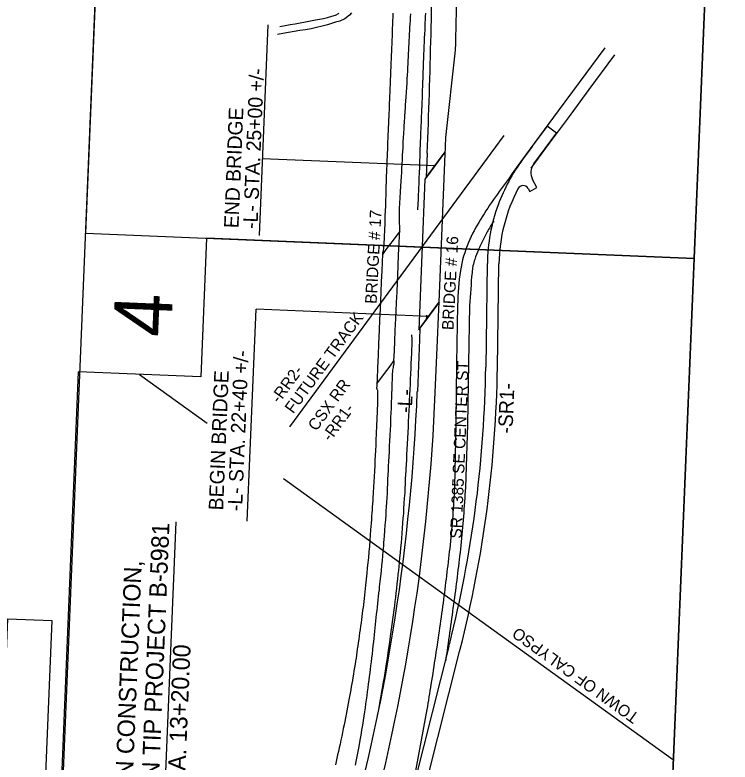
# Model space of a CAD drawing. Extents: x 2264506 to 2267635, y 507918 to 512596.
# Drawn here: x 2265629 to 2266862, y 509740 to 511027 of the extents above; entities that cross this region are included whole.
import ezdxf

# ---------------------------------------------------------------- set-up
doc = ezdxf.new("R2010")
doc.units = 0
for name, color, linetype in [('COGO Default Parcel', 7, 'Continuous'), ('Default', 7, 'Continuous'), ('Exist Structure Minor Drop Inlet Cogo Number', 7, 'Continuous'), ('Pattern 10', 7, 'Continuous'), ('Prop EOT Dash', 7, 'Continuous'), ('Prop Guardrail', 7, 'Continuous'), ('Prop Lane Arrow CELL', 7, 'Continuous'), ('Prop Structure Anchor Unit CELL', 7, 'Continuous'), ('Prop Superelevation Label', 7, 'Continuous')]:
    doc.layers.add(name, color=color, linetype=linetype)

msp = doc.modelspace()

# ---------------------------------------------------------------- linework, layer by layer
at = {"layer": 'COGO Default Parcel'}
for points in [[(2266800.3, 510607.5), (2266862.2, 512106.3), (2266024.4, 512140.9), (2266014.5, 511901.8), (2265803.2, 511910.6), (2265751.2, 510650.9)], [(2266744.1, 509248.2), (2266800.3, 510607.5), (2265959.7, 510642.3), (2265949.8, 510403.2), (2265738.5, 510412), (2265692.2, 509291.7)]]:
    msp.add_lwpolyline(points, close=True, dxfattribs=at)
at = {"layer": 'Default'}
for points in [[(2265844.2, 510407.6), (2265960.8, 510323.5)], [(2266092.5, 510228.4), (2266763.1, 509744.3)]]:
    msp.add_lwpolyline(points, dxfattribs=at)
msp.add_lwpolyline([(2265575.7, 508983.7), (2265617.1, 509986.5), (2265692.9, 509983.3), (2265651.5, 508980.6)], close=True, dxfattribs=at)
at = {"layer": 'Exist Structure Minor Drop Inlet Cogo Number'}
for p, q in [((2266065.3, 511009.8), (2266050.3, 510646.7)), ((2266353.1, 510766.8), (2266055.8, 510779.1)), ((2266029.9, 510154.4), (2266045, 510519.7)), ((2266342.4, 510507.4), (2266045, 510519.7)), ((2265884.5, 509605.1), (2265907.1, 510153.7))]:
    msp.add_line(p, q, dxfattribs=at)
at = {"layer": 'Pattern 10'}
msp.add_line((2266103.3, 510317.2), (2266472.5, 510819.4), dxfattribs=at)
at = {"layer": 'Prop EOT Dash'}
msp.add_lwpolyline([(2265695, 509291.6), (2265813.1, 512149.6), (2266862.2, 512106.3), (2266744.1, 509248.2)], close=True, dxfattribs=at)
at = {"layer": 'Prop Guardrail'}
for p, q in [((2266372.1, 510815.9), (2266389, 510966.1)), ((2266547, 510835.3), (2266521.2, 510800.8)), ((2266563.1, 510823.4), (2266547, 510835.3)), ((2266520.9, 510800), (2266504.6, 510778)), ((2266521.2, 510800.8), (2266520.7, 510800)), ((2266520.7, 510800), (2266520.9, 510800)), ((2266338.3, 510746.6), (2266371.2, 510791.3)), ((2266340, 510788.8), (2266338.3, 510746.6)), ((2266528.9, 510729.8), (2266521.7, 510743.6)), ((2266513.9, 510728.1), (2266517.2, 510722.9)), ((2266517.2, 510722.9), (2266528.9, 510729.8)), ((2266462.4, 510699.4), (2266462.2, 510699.5)), ((2266443.7, 510598.5), (2266441.7, 510463)), ((2266461.7, 510462.2), (2266463.7, 510598.2)), ((2266463.7, 510598.2), (2266463.7, 510598.2)), ((2266360.4, 510531.9), (2266327.6, 510487.2)), ((2266359.4, 510507), (2266360.4, 510531.9)), ((2266357.7, 510466.5), (2266359.4, 510507)), ((2266327.6, 510487.2), (2266326.8, 510467.8)), ((2266326.8, 510467.8), (2266323.1, 510377.9)), ((2266354, 510376.6), (2266357.7, 510466.5)), ((2266357.7, 510466.5), (2266357.7, 510466.5)), ((2266441.7, 510463), (2266441.1, 510420.2)), ((2266461.1, 510419.9), (2266461.7, 510462.2)), ((2266377.5, 509938.8), (2266309.8, 509670.6)), ((2266329.1, 509665.7), (2266396, 509930.1)), ((2266396, 509930.1), (2266396.9, 509933.9))]:
    msp.add_line(p, q, dxfattribs=at)
msp.add_lwpolyline([(2266523.7, 510770.2), (2266523.7, 510770.2), (2266563.1, 510823.4)], dxfattribs=at)
for centre, radius, start, end in [((2255163.6, 511250.5), 11186, 357.63416, 359.73109), ((2255163.6, 511250.5), 11229, 358.54854, 359.57091), ((2255163.6, 511250.5), 11217, 357.65367, 357.77953), ((2266753.7, 510593.4), 310, 143.4649, 160), ((2266543.8, 510755.3), 25, 143.465, 207.8122), ((2266753.7, 510593.4), 290, 152.4536, 179.0609), ((2266505.4, 510722.9), 10, 31.5739, 152.4536), ((2266753.7, 510593.9), 310, 160.0914, 179.154), ((2264351.3, 510451.1), 2090, 346.3966, 359.154), ((2264351.3, 510451.1), 2110, 345.8113, 359.154), ((2262840, 510521.8), 3486, 344.7422, 357.6342), ((2262840, 510521.8), 3517, 344.7004, 357.6342), ((2264351.3, 510451.1), 2090, 345.8113, 346.3966)]:
    msp.add_arc(centre, radius, start, end, dxfattribs=at)
at = {"layer": 'Prop Lane Arrow CELL'}
for p, q in [((2266485.2, 510751.2), (2266502, 510774.5)), ((2266485.2, 510751.2), (2266484.5, 510750.3)), ((2266339.5, 509830.1), (2266317, 509707.7))]:
    msp.add_line(p, q, dxfattribs=at)
for points in [[(2266209.8, 511030.6), (2266206.2, 511026.7), (2266198, 511020.4), (2266189.2, 511016.5), (2266182.2, 511014.3), (2266175.3, 511012.2), (2266168.4, 511010), (2266158.9, 511007.7), (2266149.5, 511005.4), (2266140, 511003.1), (2266130.3, 511001.5), (2266120.6, 510999.9), (2266110.8, 510998.3), (2266101.1, 510996.7), (2266091.4, 510995.1), (2266081.7, 510993.5)], [(2266086.2, 511007.1), (2266095, 511008.7), (2266103.7, 511010.3), (2266112.5, 511011.9), (2266121.2, 511013.5), (2266130, 511015.1), (2266138.7, 511016.7), (2266147.4, 511018.4), (2266154.3, 511019.7), (2266161.2, 511021.1), (2266168.1, 511022.4), (2266175.9, 511024.6), (2266181.9, 511026.3), (2266188.1, 511030.2)], [(2266280.9, 511029.9), (2266280.7, 511023.5), (2266280.4, 511017), (2266280.2, 511010.3), (2266279.9, 511003.5), (2266279.6, 510996.8), (2266279.4, 510990.1), (2266279.1, 510983.5), (2266278.8, 510976.9), (2266278.5, 510970.4), (2266278.3, 510964), (2266278, 510957.7), (2266277.8, 510951.3), (2266277.6, 510944.6), (2266277.3, 510937.5), (2266277, 510930), (2266276.7, 510922.5), (2266276.4, 510915), (2266276.1, 510907.7), (2266275.7, 510900.6), (2266275.4, 510893.7), (2266275.2, 510887.1), (2266274.9, 510881), (2266274.7, 510875.2), (2266274.4, 510869.5), (2266274.2, 510863.7), (2266274, 510857.8), (2266273.8, 510851.7), (2266273.5, 510845.6), (2266273.3, 510839.4), (2266273, 510833.2), (2266272.7, 510827), (2266272.4, 510820.8), (2266272.2, 510814.4), (2266271.9, 510807.9), (2266271.6, 510801.4), (2266271.4, 510795), (2266271.1, 510788.9), (2266270.9, 510783.3), (2266270.7, 510778.1), (2266270.5, 510772.9), (2266270.3, 510767.5), (2266270.1, 510761.8), (2266269.8, 510755.9), (2266269.6, 510749.9), (2266269.4, 510743.9), (2266269.2, 510738), (2266269, 510732.1), (2266268.8, 510726.3), (2266268.7, 510720.6), (2266268.5, 510715), (2266268.3, 510709.5), (2266268.1, 510704), (2266267.9, 510698.4), (2266267.6, 510688.9), (2266267.3, 510681.2), (2266267.1, 510675.6), (2266266.9, 510670.1), (2266266.8, 510664.7), (2266266.6, 510659.3), (2266266.3, 510653.8), (2266266.1, 510648.3), (2266265.8, 510642.6), (2266265.3, 510633.2), (2266265, 510628), (2266264.6, 510624.7), (2266264, 510621.1), (2266263.4, 510618.1), (2266263.1, 510616.3), (2266263, 510615.3), (2266263, 510614.8)], [(2266292.6, 510654.5), (2266292.6, 510656), (2266292.6, 510658.8), (2266292.6, 510662.7), (2266292.4, 510667.6), (2266292.2, 510673), (2266292.1, 510678.9), (2266292.2, 510685.6), (2266292.5, 510693.6), (2266292.9, 510702.5), (2266293.4, 510712), (2266294, 510721.9), (2266294.5, 510731.8), (2266295.1, 510740.8), (2266295.6, 510747.7), (2266296.1, 510756.2), (2266296.5, 510762.4), (2266296.9, 510769.9), (2266297.3, 510777.8), (2266297.7, 510785.1), (2266298.1, 510791.9), (2266298.4, 510798), (2266298.6, 510803.8), (2266298.9, 510809.2), (2266299.2, 510814.4), (2266299.8, 510823.7), (2266300.2, 510830.7), (2266300.6, 510835.7), (2266301, 510842.4), (2266301.5, 510851.1), (2266302.2, 510860.9), (2266302.5, 510866.1), (2266302.9, 510871.9), (2266303.3, 510878.3), (2266303.7, 510885.6), (2266304.3, 510893.6), (2266304.8, 510901.8), (2266305.3, 510909.5), (2266305.7, 510916.7), (2266306.1, 510923.4), (2266306.4, 510929.9), (2266306.7, 510936.3), (2266307.1, 510942.5), (2266307.4, 510948.6), (2266307.7, 510954.6), (2266307.9, 510960.5), (2266308.2, 510966.2), (2266308.4, 510971.8), (2266308.7, 510977.3), (2266309, 510982.9), (2266309.3, 510988.5), (2266309.7, 510994.1), (2266310, 510999.9), (2266310.4, 511005.6), (2266310.8, 511011.5), (2266311.1, 511017.5), (2266311.5, 511023.4), (2266311.9, 511029.1)], [(2266337, 511030.2), (2266336.7, 511024.5), (2266336.5, 511019), (2266336.2, 511013.5), (2266335.9, 511007.6), (2266335.7, 511001.1), (2266335.4, 510994.3), (2266335.1, 510987.2), (2266334.8, 510980.1), (2266334.5, 510973.1), (2266334.2, 510966.1), (2266333.9, 510959.5), (2266333.7, 510953.6), (2266333.3, 510943.8), (2266332.9, 510934.6), (2266332.7, 510929.3), (2266332.5, 510923.6), (2266332.3, 510917.5), (2266332, 510911.1), (2266331.8, 510904.4), (2266331.6, 510897.4), (2266331.3, 510890.4), (2266331.1, 510883.5), (2266330.8, 510876.9), (2266330.6, 510870.4), (2266330.3, 510864.1), (2266330.1, 510858.1), (2266329.8, 510852.4), (2266329.6, 510846.9), (2266329.4, 510841.5), (2266329.1, 510836.1), (2266328.9, 510830.7), (2266328.7, 510825.2), (2266328.5, 510819.8), (2266328.3, 510814.5), (2266328.1, 510809.3), (2266327.9, 510804.3), (2266327.5, 510794.3), (2266327.1, 510784.3), (2266326.8, 510774.4), (2266326.5, 510764.6), (2266326.2, 510755), (2266325.8, 510745.5), (2266325.6, 510740.6), (2266325.4, 510735.4), (2266325.2, 510729.7), (2266325, 510723.7), (2266324.7, 510717), (2266324.3, 510709.4), (2266323.8, 510700.8), (2266323.2, 510691.4)], [(2266502, 510774.5), (2266534, 510817.8), (2266566.6, 510861.8), (2266602.5, 510910.4), (2266646.8, 510970.2)], [(2266662.9, 510958), (2266618.8, 510898.4), (2266582.8, 510849.5), (2266550.1, 510805.8), (2266518.6, 510762.7)], [(2266392.5, 510526.9), (2266390.6, 510427), (2266389.2, 510321.4), (2266387, 510213.8)], [(2266413, 510525.8), (2266411.1, 510426.9), (2266409.6, 510321.1), (2266405.9, 510212.7)], [(2266339, 510509.6), (2266338.8, 510506.6), (2266338.5, 510502.1)], [(2266253.2, 509812.9), (2266254.5, 509819.5), (2266256, 509827.5), (2266257.6, 509836.2), (2266259.2, 509844.7), (2266260.6, 509853), (2266262.1, 509861.3), (2266263.6, 509869.5), (2266264.9, 509877.5), (2266266.3, 509885.3), (2266267.5, 509892.9), (2266268.7, 509900.6), (2266270, 509908.9), (2266271.4, 509918), (2266272.8, 509927.6), (2266273.6, 509932.5), (2266275, 509942.2), (2266276.2, 509951.1), (2266277.4, 509959.7), (2266278.6, 509968.3), (2266279.8, 509976.8), (2266281, 509985.2), (2266282.1, 509993.5), (2266283.1, 510001.6), (2266284.1, 510009.3), (2266284.9, 510016.3), (2266285.8, 510023.1), (2266286.7, 510030.6), (2266287.6, 510038.6), (2266288.5, 510046.7), (2266289.4, 510054.8), (2266290.2, 510062.6), (2266290.9, 510069.9), (2266291.6, 510076.6), (2266292.3, 510083.6), (2266293.1, 510091.7), (2266294, 510100.3), (2266294.8, 510108.8), (2266295.5, 510117.1), (2266296.2, 510125.3), (2266296.9, 510133.6), (2266297.6, 510142.4), (2266298.3, 510151.3), (2266298.9, 510159.8), (2266299.5, 510168.1), (2266300, 510176.3), (2266300.6, 510184.8), (2266301.2, 510194.1), (2266301.8, 510203.2), (2266302.2, 510211.3), (2266302.6, 510219), (2266302.9, 510227.1), (2266303.3, 510235.9), (2266303.6, 510240.8), (2266303.9, 510246), (2266304.1, 510251.2), (2266304.7, 510260.8), (2266305.2, 510269.4), (2266305.7, 510278.4), (2266306.2, 510288), (2266306.7, 510297.8), (2266307.2, 510307.6), (2266307.7, 510317.1), (2266308.1, 510326.2), (2266308.5, 510335.5), (2266308.9, 510344.9), (2266309.3, 510354), (2266309.7, 510362.8), (2266310.1, 510371.9), (2266310.5, 510381.3), (2266311, 510390.5), (2266311.4, 510399.5), (2266311.8, 510408.7), (2266312.3, 510418), (2266312.7, 510426.6), (2266313.1, 510434.8), (2266313.6, 510444.2), (2266313.8, 510449.4), (2266314.2, 510458.3), (2266314.4, 510463.8), (2266314.4, 510467.3), (2266314.1, 510470.6), (2266313.8, 510473.5), (2266313.7, 510476)], [(2266282.8, 510430.7), (2266282.8, 510428.2), (2266282.8, 510426.9), (2266282.8, 510426.6), (2266282.7, 510426.1), (2266282.5, 510425), (2266282.1, 510423.5), (2266281.6, 510421.5), (2266281.1, 510419.2), (2266280.7, 510417), (2266280.4, 510414.8), (2266280.1, 510412.8), (2266279.9, 510408.6), (2266279.6, 510400.2), (2266279.2, 510390.3), (2266278.9, 510381.9), (2266278.6, 510374.4), (2266278.4, 510367.5), (2266278.1, 510359.9), (2266277.7, 510350.2), (2266277.3, 510340.7), (2266277, 510333.6), (2266276.8, 510327.2), (2266276.5, 510320), (2266276.1, 510311.8), (2266275.7, 510302.6), (2266275.2, 510293), (2266274.7, 510283.8), (2266274.3, 510274.8), (2266273.9, 510266), (2266273.5, 510257.6), (2266273, 510249.6), (2266272.6, 510241.8), (2266272.3, 510234.3), (2266271.9, 510226.8), (2266271.6, 510219.2), (2266271.2, 510211.3), (2266270.8, 510203.1), (2266270.3, 510194.9), (2266269.8, 510186.8), (2266269.4, 510179.3), (2266269, 510172.4), (2266268.5, 510165.3), (2266267.9, 510156.8), (2266267.2, 510147.6), (2266266.5, 510138.4), (2266265.8, 510128.6), (2266265.4, 510123.3), (2266264.9, 510117.7), (2266264.5, 510112.3), (2266263.7, 510102.9), (2266263, 510095), (2266262.2, 510086.9), (2266261.4, 510078.2), (2266260.5, 510069), (2266259.5, 510059.5), (2266258.5, 510050.4), (2266257.5, 510041.5), (2266257, 510036.5), (2266256.3, 510031), (2266255.7, 510025.1), (2266255, 510018.9), (2266254.3, 510012.8), (2266253.6, 510006.7), (2266253, 510000.6), (2266252.3, 509994.6), (2266251.7, 509988.6), (2266251.1, 509982.6), (2266250.5, 509976.8), (2266249.9, 509970.9), (2266249.3, 509965), (2266248.6, 509959), (2266248, 509952.9), (2266247.3, 509946.6), (2266246.5, 509940.1), (2266245.7, 509933.2), (2266244.9, 509926), (2266244, 509918.8), (2266243.2, 509912), (2266242.4, 509905.5), (2266241.6, 509899.4), (2266240.9, 509893.4), (2266240.1, 509887.1), (2266239.3, 509880.7), (2266238.5, 509874.1), (2266237.6, 509867.4), (2266236.7, 509860.7), (2266235.8, 509853.9), (2266234.9, 509847), (2266233.9, 509840.1), (2266232.9, 509833), (2266231.9, 509825.9), (2266230.8, 509818.5), (2266229.6, 509811), (2266228.4, 509803), (2266227, 509794.7), (2266225.6, 509786), (2266224.2, 509777.5), (2266222.9, 509770), (2266221.7, 509763.3), (2266220.5, 509757.5), (2266219.5, 509752), (2266218.3, 509746.3), (2266217.1, 509740.3), (2266215.9, 509734.1)], [(2266253.1, 510390.7), (2266253.1, 510389.5), (2266253.1, 510388.5), (2266253.1, 510387.4), (2266253, 510386.2), (2266252.9, 510385.1), (2266252.9, 510384.7), (2266252.8, 510384.4), (2266252.8, 510384.1), (2266252.9, 510383.6), (2266253.2, 510383), (2266253.5, 510382.3), (2266253.9, 510381.4), (2266254.2, 510380.3), (2266254.3, 510378.9), (2266254.3, 510375.8), (2266254.4, 510372.3), (2266254.4, 510368.8), (2266254.4, 510365.7), (2266254.4, 510362.6), (2266254.2, 510356.3), (2266253.8, 510346.4), (2266253.6, 510340.8), (2266253.4, 510334.7), (2266253.1, 510328.2), (2266252.8, 510321.7), (2266252.6, 510315.6), (2266252.3, 510310), (2266252.1, 510304.8), (2266251.7, 510295.1), (2266251.3, 510285.6), (2266250.8, 510276.5), (2266250.4, 510267.9), (2266250, 510259.4), (2266249.6, 510250.4), (2266249.1, 510241), (2266248.6, 510231.6), (2266248, 510222.3), (2266247.5, 510213.2), (2266246.9, 510204.1), (2266246.4, 510194.5), (2266246.1, 510189.5), (2266245.8, 510184.5), (2266245.4, 510179.4), (2266245, 510174.2), (2266244.6, 510168.9), (2266244.2, 510163.3), (2266243.8, 510157.5), (2266243.3, 510151.3), (2266242.9, 510145.3), (2266242.5, 510139.8), (2266241.7, 510130.3), (2266241.1, 510121.4), (2266240.3, 510111.8), (2266239.5, 510101.8), (2266238.6, 510092.2), (2266237.7, 510082.9), (2266236.8, 510074), (2266235.9, 510064.9), (2266235.4, 510060.1), (2266234.9, 510054.9), (2266234.3, 510049.6), (2266233.7, 510044.2), (2266233.1, 510038.6), (2266232.5, 510032.8), (2266231.9, 510027.1), (2266231.2, 510021.6), (2266230.6, 510016.2), (2266230, 510011), (2266229.4, 510005.8), (2266228.7, 510000.7), (2266228.1, 509995.5), (2266227.4, 509990.2), (2266226.7, 509984.9), (2266226, 509979.5), (2266225.2, 509973.9), (2266224.4, 509968.1), (2266223.6, 509962.3), (2266222.8, 509956.5), (2266222, 509950.8), (2266221.2, 509945.1), (2266220.4, 509939.6), (2266219.6, 509934.2), (2266218.9, 509928.9), (2266218.1, 509923.9), (2266217.4, 509918.8), (2266216.6, 509913.5), (2266215.7, 509908), (2266214.8, 509902.3), (2266213.8, 509896.5), (2266212.9, 509890.8), (2266211.9, 509885.4), (2266211, 509880), (2266210.1, 509874.7), (2266209.1, 509869.4), (2266208.2, 509863.9), (2266207.2, 509858.4), (2266206.2, 509852.7), (2266205.1, 509846.8), (2266204, 509840.7), (2266202.8, 509834.4), (2266201.6, 509828), (2266200.3, 509821.7), (2266199.1, 509815.6), (2266197.9, 509809.5), (2266196.7, 509803.4), (2266195.4, 509797.1), (2266194, 509790.6), (2266192.6, 509783.9), (2266191.2, 509777.1), (2266189.8, 509770.5), (2266188.4, 509764.1), (2266187, 509757.9), (2266185.7, 509751.8), (2266184.4, 509746), (2266183.1, 509740.4), (2266181.9, 509735)]]:
    msp.add_lwpolyline(points, dxfattribs=at)
for points in [[(2266484.5, 510750.3), (2266457.7, 510713.5), (2266431.9, 510674.3), (2266411.3, 510635.1), (2266397.2, 510586.3), (2266392.5, 510526.9)], [(2266454.8, 510671.8), (2266449.9, 510664.1), (2266444.7, 510655.2), (2266439.8, 510646.3), (2266435.2, 510637.1), (2266430.8, 510627.7), (2266428.4, 510622.3), (2266422, 510605.8), (2266419, 510594.6), (2266417.9, 510588.8), (2266417.3, 510583.1), (2266413, 510525.8)], [(2266387, 510213.8), (2266384, 510164.1), (2266379.5, 510113.7), (2266374, 510066.5), (2266368.1, 510019.4), (2266361.5, 509971.1), (2266354.2, 509922.7), (2266346.6, 509873.4), (2266339.5, 509830.1)], [(2266405.9, 510212.7), (2266402.5, 510162.9), (2266397.9, 510112.6), (2266392.4, 510064.6), (2266386.2, 510016.8), (2266379.4, 509968.6), (2266372.4, 509918.9), (2266371.6, 509913.6)]]:
    msp.add_spline(points, degree=3, dxfattribs=at)
at = {"layer": 'Prop Superelevation Label'}
for p, q in [((2266371.2, 510791.3), (2266365.9, 510784.1)), ((2266365.9, 510784.1), (2266340.4, 510749.5)), ((2266340.4, 510749.5), (2266338.3, 510746.6)), ((2266336.2, 510743.7), (2266325.5, 510484.4)), ((2266338.3, 510746.6), (2266336.2, 510743.7)), ((2266355.1, 510524.7), (2266360.4, 510531.9)), ((2266329.7, 510490.1), (2266355.1, 510524.7)), ((2266327.6, 510487.2), (2266329.7, 510490.1)), ((2266325.5, 510484.4), (2266327.6, 510487.2))]:
    msp.add_line(p, q, dxfattribs=at)
for points in [[(2266360.4, 510531.9), (2266360.4, 510531.9), (2266371, 510787.5)], [(2266262.4, 510601.8), (2266261.6, 510585.5), (2266260.8, 510567.4), (2266260.1, 510549.1), (2266259.4, 510534.5), (2266258.8, 510520.5), (2266258, 510501.5), (2266257.2, 510483.8), (2266256.2, 510460.4), (2266255.3, 510440.8), (2266254.4, 510418.8), (2266253.6, 510399.2), (2266253.2, 510391), (2266253.3, 510391.2), (2266265, 510407), (2266276.1, 510422), (2266282.8, 510430.7), (2266282.8, 510430.9), (2266283.6, 510448.4), (2266284.4, 510464.9), (2266285.1, 510483.1), (2266286.1, 510503.8), (2266286.7, 510516.5), (2266287.3, 510531.6), (2266288, 510549.8), (2266288.7, 510565.6), (2266289.3, 510579.9), (2266290, 510594.3), (2266290.8, 510614), (2266291.5, 510631.3), (2266292.3, 510648.7), (2266292.6, 510654.3), (2266281.1, 510639), (2266269, 510622.5), (2266263, 510614.4), (2266262.4, 510601.8)]]:
    msp.add_lwpolyline(points, dxfattribs=at)
msp.add_arc((2255163.6, 511250.5), 11217, 357.63416, 357.65367, dxfattribs=at)

# ---------------------------------------------------------------- texts
at = {"layer": 'Default'}
for s, height, rotation, p in [('BRIDGE # 17', 20, 86.9656, (2266252.8, 510528.7)), ('BRIDGE # 16', 20, 86.9656, (2266385.2, 510483.5)), ('4', 100, 87.6342, (2265898.6, 510470.9)), ('FUTURE TRACK', 20, 53.7747, (2266109, 510338.7)), ('SR 1385 SE CENTER ST', 20, 87.6342, (2266399.2, 510124.3)), ('-RR2- ', 20, 53.7747, (2266084.8, 510356.4)), ('CSX RR', 20, 53.7747, (2266148.9, 510308.5)), ('-SR1- ', 25, 87.6342, (2266487, 510305.1)), ('-L-', 25, 86.9656, (2266313.3, 510340.7)), ('-RR1-', 20, 53.7747, (2266173.1, 510290.7)), ('TOWN OF CALYPSO', 20, 144.1748, (2266706.9, 509820.8))]:
    msp.add_text(s, height=height, rotation=rotation, dxfattribs=at).set_placement(p)
at = {"layer": 'Prop Structure Anchor Unit CELL'}
for s, height, p in [('-L- STA. 25+00 +/-', 25, (2266047.4, 510657.8)), ('END BRIDGE', 25, (2266014.7, 510659.1)), ('-L- STA. 22+40 +/- ', 25, (2266020.9, 510171.6)), ('BEGIN BRIDGE', 25, (2265988.2, 510172.9)), ('BEGIN TIP PROJECT B-5981', 30, (2265873.7, 509614.9)), ('BEGIN CONSTRUCTION,', 30, (2265828.8, 509616.8)), ('-L- STA. 13+20.00', 30, (2265918.7, 509613))]:
    msp.add_text(s, height=height, rotation=87.6342, dxfattribs=at).set_placement(p)

doc.saveas('drawing.dxf')
